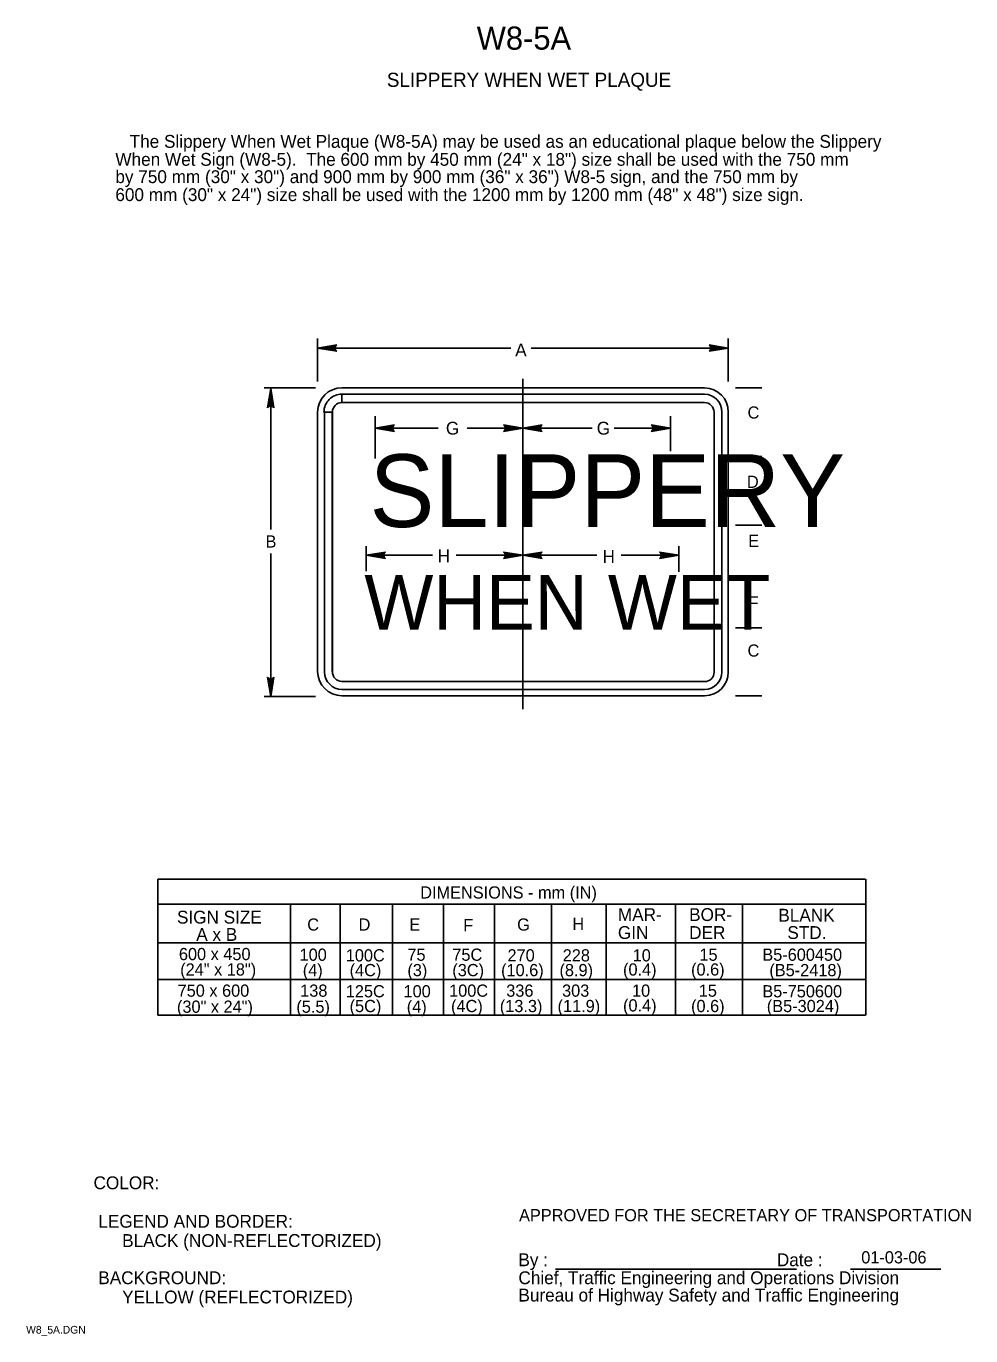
# Model space of a CAD drawing. Extents: x 0.012 to 0.196, y 0.004 to 0.259.
import ezdxf

# ---------------------------------------------------------------- set-up
doc = ezdxf.new("R2010")
doc.units = 0
for name, color, linetype in [('1', 7, 'Continuous'), ('12', 7, 'Continuous'), ('2', 7, 'Continuous'), ('3', 7, 'Continuous'), ('4', 7, 'Continuous')]:
    doc.layers.add(name, color=color, linetype=linetype)

# ---------------------------------------------------------------- blocks, each defined once
blk = doc.blocks.new('RARROW')
at = {"layer": '3'}
for p, q in [((-2.156, 0.28500000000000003), (-2.2665, 0.384625)), ((-2.2665, 0.384625), (0, 0)), ((0, 0), (-2.2665, -0.379125)), ((-2.156, 0.28500000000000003), (-2.075625, 0.12075)), ((0, 0), (-2.156, 0.28500000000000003)), ((-2.14975, -0.2705), (0, 0)), ((-2.075625, 0.12075), (0, 0)), ((0, 0), (-2.074, -0.108)), ((-2.2665, -0.379125), (-2.14975, -0.2705)), ((-2.074, -0.108), (-2.14975, -0.2705))]:
    blk.add_line(p, q, dxfattribs=at)

msp = doc.modelspace()

# ---------------------------------------------------------------- linework, layer by layer
at = {"layer": '1'}
for p, q in [((0.11543984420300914, 0.01694517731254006), (0.1624214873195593, 0.01694517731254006)), ((0.17295324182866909, 0.01694517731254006), (0.1905000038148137, 0.01694517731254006))]:
    msp.add_line(p, q, dxfattribs=at)
at = {"layer": '3'}
for p, q in [((0.069125, 0.18987500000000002), (0.069125, 0.19825)), ((0.149125, 0.18987500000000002), (0.149125, 0.19825)), ((0.10675, 0.196375), (0.069125, 0.196375)), ((0.11075, 0.196375), (0.149125, 0.196375)), ((0.109125, 0.19037500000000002), (0.109125, 0.126)), ((0.06875, 0.18862500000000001), (0.058750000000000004, 0.18862500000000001)), ((0.06, 0.161), (0.06, 0.18862500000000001)), ((0.073875, 0.18862500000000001), (0.1445, 0.18862500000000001)), ((0.1445, 0.187375), (0.073875, 0.187375)), ((0.073875, 0.187375), (0.07387569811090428, 0.18574738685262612)), ((0.07387569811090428, 0.18574738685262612), (0.073875, 0.187375)), ((0.1505, 0.18862500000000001), (0.155625, 0.18862500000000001)), ((0.069125, 0.133375), (0.069125, 0.183875)), ((0.07037500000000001, 0.183875), (0.07201621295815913, 0.18388790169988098)), ((0.07200000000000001, 0.183875), (0.07044815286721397, 0.18388790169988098)), ((0.07050000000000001, 0.183875), (0.07050000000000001, 0.13325)), ((0.07200000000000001, 0.133375), (0.07200000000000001, 0.183875)), ((0.07200000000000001, 0.133375), (0.07200000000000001, 0.183875)), ((0.0720351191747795, 0.18384855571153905), (0.0720351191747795, 0.13334855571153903)), ((0.0720351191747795, 0.13334855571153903), (0.0720351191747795, 0.18384855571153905)), ((0.0720351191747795, 0.18384855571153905), (0.0720351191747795, 0.13334855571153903)), ((0.073875, 0.18575), (0.1445, 0.18575)), ((0.146375, 0.183875), (0.146375, 0.13325)), ((0.147875, 0.13325), (0.147875, 0.183875)), ((0.149125, 0.183875), (0.149125, 0.13325)), ((0.080375, 0.183125), (0.080375, 0.174875)), ((0.137875, 0.183125), (0.137875, 0.17625)), ((0.092625, 0.18075), (0.080375, 0.18075)), ((0.09825, 0.18075), (0.109125, 0.18075)), ((0.122625, 0.18075), (0.109125, 0.18075)), ((0.12687500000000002, 0.18075), (0.137875, 0.18075)), ((0.1505, 0.17525000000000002), (0.155625, 0.17525000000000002)), ((0.1505, 0.161875), (0.155625, 0.161875)), ((0.06, 0.15637500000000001), (0.06, 0.128625)), ((0.078625, 0.15775), (0.078625, 0.152875)), ((0.0915, 0.156), (0.078625, 0.156)), ((0.096125, 0.156), (0.109125, 0.156)), ((0.1235, 0.156), (0.109125, 0.156)), ((0.12825, 0.156), (0.1395, 0.156)), ((0.1395, 0.15775), (0.1395, 0.15275)), ((0.1505, 0.151875), (0.155625, 0.151875)), ((0.1505, 0.141875), (0.155625, 0.141875)), ((0.1445, 0.131375), (0.073875, 0.131375)), ((0.06875, 0.1285), (0.058750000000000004, 0.1285)), ((0.073875, 0.129875), (0.1445, 0.129875)), ((0.1445, 0.128625), (0.073875, 0.128625)), ((0.1505, 0.128625), (0.155625, 0.128625)), ((0.038, 0.092875), (0.175875, 0.092875)), ((0.038039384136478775, 0.09287569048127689), (0.038039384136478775, 0.0663756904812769)), ((0.17593791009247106, 0.09287569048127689), (0.17593791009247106, 0.0663756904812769)), ((0.038, 0.088), (0.175875, 0.088)), ((0.06387418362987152, 0.08802738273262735), (0.06387418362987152, 0.0663756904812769)), ((0.07353938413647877, 0.08800069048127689), (0.07353938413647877, 0.0663756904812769)), ((0.08375655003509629, 0.08800069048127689), (0.08375655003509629, 0.0663756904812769)), ((0.09368984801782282, 0.08800069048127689), (0.09368984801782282, 0.0663756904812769)), ((0.10356484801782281, 0.08800069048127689), (0.10356484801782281, 0.0663756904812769)), ((0.11468984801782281, 0.08800069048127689), (0.11468984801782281, 0.0663756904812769)), ((0.1253620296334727, 0.08802738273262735), (0.1253620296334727, 0.0663756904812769)), ((0.13882622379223, 0.08802738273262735), (0.13882622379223, 0.0663756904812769)), ((0.1519163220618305, 0.08802738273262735), (0.1519163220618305, 0.0663756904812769)), ((0.038, 0.0805), (0.175875, 0.0805)), ((0.038, 0.073375), (0.175875, 0.073375)), ((0.038, 0.066375), (0.175875, 0.066375))]:
    msp.add_line(p, q, dxfattribs=at)
for centre, radius, start, end in [((0.07387500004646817, 0.1838749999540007), 0.004750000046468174, 90, 180), ((0.07387499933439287, 0.18387500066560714), 0.003499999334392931, 89.9999888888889, 180.00001111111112), ((0.14443750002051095, 0.18393750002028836), 0.004687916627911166, 359.2361, 89.23610000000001), ((0.14443749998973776, 0.18393749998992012), 0.003438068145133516, 358.95837222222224, 88.95837222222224), ((0.07387569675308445, 0.1838879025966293), 0.0018594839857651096, 90, 180), ((0.1444956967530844, 0.1838879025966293), 0.0018594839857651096, 0, 90), ((0.07387499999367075, 0.13337499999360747), 0.004749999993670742, 180, 270), ((0.07387500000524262, 0.13325000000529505), 0.003375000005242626, 180, 270), ((0.07392547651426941, 0.13329877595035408), 0.001891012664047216, 178.49155000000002, 268.49155), ((0.14450000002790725, 0.13324999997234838), 0.004624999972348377, 270, 0), ((0.1444999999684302, 0.1332500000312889), 0.0033750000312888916, 270, 0), ((0.14449999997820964, 0.1332500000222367), 0.0018750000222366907, 270, 0)]:
    msp.add_arc(centre, radius, start, end, dxfattribs=at)

# ---------------------------------------------------------------- block references
at = {"layer": '3', "xscale": 0.0016545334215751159}
for p, yscale, rotation in [((0.069125, 0.196375), 0.0016366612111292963, 180), ((0.06, 0.1885), 0.0016366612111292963, 90), ((0.080375, 0.18075), -0.0016366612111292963, -180), ((0.109125, 0.18075), -0.0016366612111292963, -180), ((0.078625, 0.156), -0.0016366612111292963, -180), ((0.109125, 0.156), -0.0016366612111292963, -180), ((0.06, 0.1285), 0.0016366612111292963, -90)]:
    msp.add_blockref('RARROW', p, dxfattribs=dict(at, yscale=yscale, rotation=rotation))
at = {"layer": '3', "xscale": 0.0016545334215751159, "yscale": 0.0016366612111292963}
for p in [(0.149125, 0.196375), (0.109125, 0.18075), (0.137875, 0.18075), (0.109125, 0.156), (0.1395, 0.156)]:
    msp.add_blockref('RARROW', p, dxfattribs=at)

# ---------------------------------------------------------------- texts
at = {"layer": '1'}
for s, height, p in [('W8-5A', 0.0045000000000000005, (0.100125, 0.2545)), ('SLIPPERY WHEN WET PLAQUE', 0.00275025, (0.082625, 0.24725)), ('COLOR:', 0.0024997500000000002, (0.025500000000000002, 0.0325)), ('APPROVED FOR THE SECRETARY OF TRANSPORTATION', 0.0023752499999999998, (0.108375, 0.02625)), (' LEGEND AND BORDER:', 0.0024997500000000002, (0.025500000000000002, 0.025)), ('      BLACK (NON-REFLECTORIZED)', 0.0024997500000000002, (0.025500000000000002, 0.02125)), ('By :                                                Date :', 0.0024997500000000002, (0.10825, 0.0175)), (' BACKGROUND:', 0.0024997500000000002, (0.025500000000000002, 0.014)), ('Chief, Traffic Engineering and Operations Division', 0.0024997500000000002, (0.10825, 0.014)), ('      YELLOW (REFLECTORIZED)', 0.0024997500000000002, (0.025500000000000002, 0.01025)), ('Bureau of Highway Safety and Traffic Engineering', 0.0024997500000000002, (0.10825, 0.010625)), ('W8_5A.DGN', 0.0015, (0.012375, 0.004375))]:
    msp.add_text(s, height=height, dxfattribs=at).set_placement(p)
at = {"layer": '12'}
for s, height, p in [('SLIPPERY', 0.01416, (0.07925, 0.1615)), ('WHEN WET', 0.01064025, (0.07825, 0.14150000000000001))]:
    msp.add_text(s, height=height, dxfattribs=at).set_placement(p)
at = {"layer": '2'}
for s, p in [('   The Slippery When Wet Plaque (W8-5A) may be used as an educational plaque below the Slippery ', (0.029750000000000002, 0.235375)), ('When Wet Sign (W8-5).  The 600 mm by 450 mm (24" x 18") size shall be used with the 750 mm ', (0.029750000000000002, 0.231875)), ('by 750 mm (30" x 30") and 900 mm by 900 mm (36" x 36") W8-5 sign, and the 750 mm by', (0.029750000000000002, 0.2285)), ('600 mm (30" x 24") size shall be used with the 1200 mm by 1200 mm (48" x 48") size sign.', (0.029750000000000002, 0.225))]:
    msp.add_text(s, height=0.0024997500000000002, dxfattribs=at).set_placement(p)
at = {"layer": '3'}
for s, height, p in [('A', 0.0024997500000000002, (0.107625, 0.19475)), ('C', 0.0023752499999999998, (0.152875, 0.182625)), ('G', 0.0024997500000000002, (0.094125, 0.1795)), ('G', 0.0024997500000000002, (0.1235, 0.1795)), ('D', 0.0023752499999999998, (0.15275, 0.169125)), ('B', 0.0023752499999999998, (0.059000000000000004, 0.1575)), ('E', 0.0023752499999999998, (0.153, 0.15762500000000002)), ('H', 0.0024997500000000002, (0.0925, 0.154625)), ('H', 0.0024997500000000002, (0.124625, 0.1545)), ('F', 0.0024997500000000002, (0.153, 0.1455)), ('C', 0.0023752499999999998, (0.152875, 0.13625)), ('DIMENSIONS - mm (IN)', 0.0023752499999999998, (0.089125, 0.089125)), ('SIGN SIZE', 0.0024997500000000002, (0.04175, 0.08425)), ('MAR-', 0.0024997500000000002, (0.12762500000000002, 0.08475)), ('BOR-', 0.0024997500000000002, (0.14150000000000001, 0.08475)), ('BLANK', 0.0024997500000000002, (0.15887500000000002, 0.084625)), ('C', 0.0023752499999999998, (0.067125, 0.082875)), ('D', 0.0023752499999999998, (0.077125, 0.082875)), ('E', 0.0023752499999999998, (0.08700000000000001, 0.082875)), ('F', 0.0023752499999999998, (0.0975, 0.08275)), ('G', 0.0023752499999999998, (0.108, 0.082875)), ('H', 0.0023752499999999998, (0.11875000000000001, 0.083)), ('A x B', 0.0024997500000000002, (0.0455, 0.080875)), ('GIN', 0.0024997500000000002, (0.12762500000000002, 0.08125)), ('DER', 0.0024997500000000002, (0.14150000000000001, 0.08125)), ('STD.', 0.0024997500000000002, (0.160625, 0.08125)), ('600 x 450', 0.0023752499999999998, (0.042125, 0.077125)), ('100', 0.0023752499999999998, (0.065625, 0.077)), ('100C', 0.0023752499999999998, (0.074625, 0.076875)), ('75', 0.0023752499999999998, (0.08662500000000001, 0.077)), ('75C', 0.0023752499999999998, (0.095375, 0.077)), ('270', 0.0023752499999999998, (0.106125, 0.076875)), ('228', 0.0023752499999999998, (0.116875, 0.076875)), ('10', 0.0023752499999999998, (0.1305, 0.076875)), ('15', 0.0023752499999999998, (0.14350000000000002, 0.077)), ('B5-600450', 0.0023752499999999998, (0.15575, 0.077)), ('(24" x 18")', 0.0023752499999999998, (0.042375, 0.074125)), ('(0.4)', 0.0023752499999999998, (0.128625, 0.074125)), ('(0.6)', 0.0023752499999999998, (0.141875, 0.074125)), ('(4)', 0.0023752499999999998, (0.06625, 0.074)), ('(4C)', 0.0023752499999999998, (0.075375, 0.074)), ('(3)', 0.0023752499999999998, (0.08662500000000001, 0.074)), ('(3C)', 0.0023752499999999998, (0.095375, 0.074)), ('(10.6)', 0.0023752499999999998, (0.104875, 0.074)), ('(8.9)', 0.0023752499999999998, (0.11625, 0.074)), ('(B5-2418)', 0.0023752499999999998, (0.15712500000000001, 0.074)), ('750 x 600', 0.0023752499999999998, (0.041875, 0.07)), ('138', 0.0023752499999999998, (0.06575, 0.07)), ('125C', 0.0023752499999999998, (0.074625, 0.069875)), ('100', 0.0023752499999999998, (0.085875, 0.069875)), ('100C', 0.0023752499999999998, (0.09475, 0.07)), ('336', 0.0023752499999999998, (0.105875, 0.07)), ('303', 0.0023752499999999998, (0.11675, 0.07)), ('10', 0.0023752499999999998, (0.130375, 0.07)), ('15', 0.0023752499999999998, (0.143375, 0.07)), ('B5-750600', 0.0023752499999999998, (0.15575, 0.069875)), ('(30" x 24")', 0.0023752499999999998, (0.04175, 0.066875)), ('(5.5)', 0.0023752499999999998, (0.065, 0.066875)), ('(5C)', 0.0023752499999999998, (0.075375, 0.067)), ('(4)', 0.0023752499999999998, (0.08650000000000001, 0.066875)), ('(4C)', 0.0023752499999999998, (0.095125, 0.067)), ('(13.3)', 0.0023752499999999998, (0.104625, 0.067)), ('(11.9)', 0.0023752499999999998, (0.115875, 0.067)), ('(0.4)', 0.0023752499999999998, (0.128625, 0.067125)), ('(0.6)', 0.0023752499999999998, (0.141875, 0.067)), ('(B5-3024)', 0.0023752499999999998, (0.15662500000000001, 0.067))]:
    msp.add_text(s, height=height, dxfattribs=at).set_placement(p)
at = {"layer": '4'}
msp.add_text('01-03-06', height=0.0023752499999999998, dxfattribs=at).set_placement((0.1750193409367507, 0.018045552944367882))

doc.saveas('drawing.dxf')
